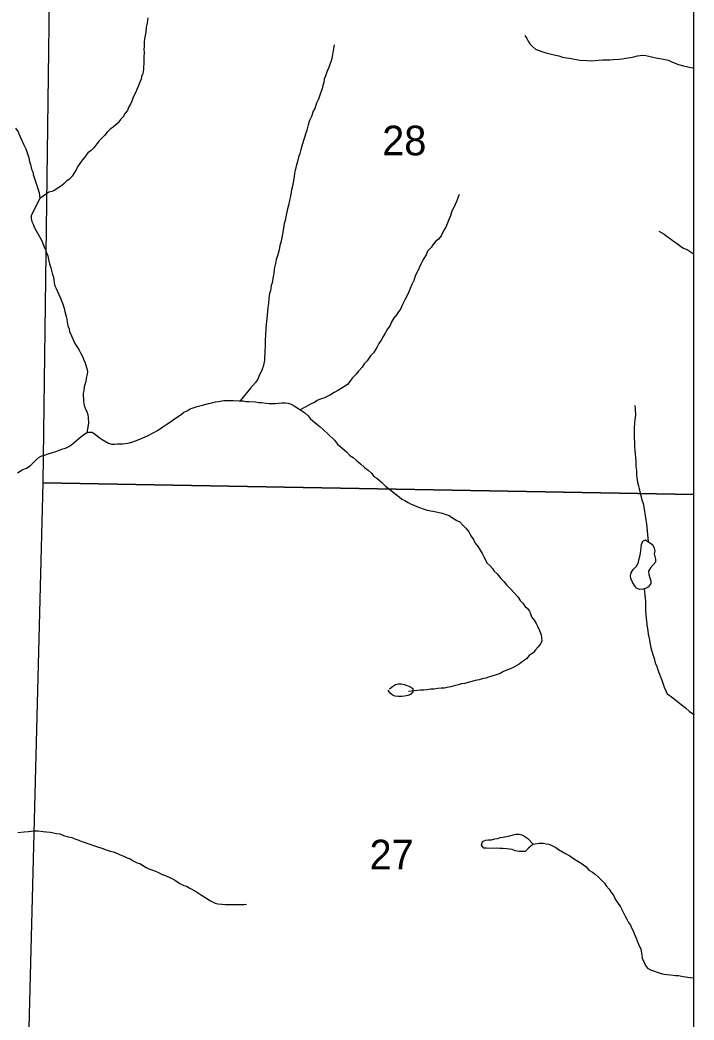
# Model space of a CAD drawing. Extents: x -10 to 158, y 8 to 33.
# Drawn here: x 30.449 to 31.4, y 15.63 to 17.041 of the extents above; entities that cross this region are included whole.
import ezdxf

# ---------------------------------------------------------------- set-up
doc = ezdxf.new("R2010")
doc.units = 0
for name, color, linetype in [('GM_X_Corporation', 7, 'Continuous'), ('GM_X_Minor_River', 7, 'Continuous'), ('GM_X_Section_Text', 7, 'Continuous')]:
    doc.layers.add(name, color=color, linetype=linetype)

msp = doc.modelspace()

# ---------------------------------------------------------------- linework, layer by layer
at = {"layer": 'GM_X_Corporation'}
for points in [[(29.6227, 14.1), (31.4, 14.1), (31.4, 20.9), (29.731, 20.9), (29.7244, 20.2649), (29.6982, 19.2496), (29.6981, 19.2461), (29.6974, 19.2018), (29.6957, 19.0991), (29.6992, 18.9556), (29.697, 18.9465), (29.6949, 18.8465), (29.6846, 18.5133), (29.6817, 18.3306), (29.6804, 18.2238), (29.6572, 17.4131), (29.6504, 16.6563), (29.6434, 16.3848), (29.6318, 15.4937)], [(31.4, 16.3712), (31.4, 17.3866), (30.4945, 17.3927), (30.4815, 16.3875)], [(31.4, 15.3662), (31.4, 16.3712), (30.4815, 16.3875), (30.4552, 15.381)]]:
    msp.add_lwpolyline(points, close=True, dxfattribs=at)
at = {"layer": 'GM_X_Minor_River'}
for points in [[(30.6294, 17.0437), (30.6284, 17.0361), (30.627, 17.0304), (30.6264, 17.0235), (30.6246, 17.014), (30.6243, 17.0095), (30.6244, 17.0034), (30.6238, 16.9992), (30.6242, 16.9954), (30.624, 16.9878), (30.6237, 16.9829), (30.6231, 16.9711), (30.6225, 16.9654), (30.6206, 16.9612), (30.62, 16.9574), (30.6181, 16.9532), (30.6156, 16.9467), (30.6138, 16.9429), (30.6123, 16.9391), (30.6101, 16.9349), (30.6083, 16.9303), (30.6069, 16.9261), (30.6051, 16.9219), (30.6021, 16.9173), (30.6007, 16.9131), (30.5973, 16.9092), (30.5944, 16.9043), (30.5907, 16.9004), (30.5874, 16.8958), (30.5806, 16.8896), (30.5765, 16.8865), (30.5721, 16.8826), (30.5684, 16.8776), (30.5606, 16.8703), (30.5576, 16.8661), (30.5532, 16.8603), (30.5494, 16.8568), (30.545, 16.8533), (30.5413, 16.8487), (30.5372, 16.8433), (30.5342, 16.8395), (30.5302, 16.8337), (30.5283, 16.8295), (30.525, 16.8242), (30.5225, 16.8203), (30.5187, 16.8161), (30.515, 16.8137), (30.5109, 16.8095), (30.5061, 16.8056), (30.5016, 16.8029), (30.4978, 16.8002), (30.4941, 16.7986), (30.4896, 16.7977), (30.4772, 16.7888), (30.4648, 16.7651), (30.4648, 16.7609), (30.4657, 16.7564), (30.4676, 16.7526), (30.4696, 16.7477), (30.477, 16.7342), (30.4798, 16.7293), (30.4837, 16.7195), (30.4857, 16.7158), (30.4865, 16.712), (30.4881, 16.7082), (30.4893, 16.7029), (30.4906, 16.6965), (30.4925, 16.6912)], [(31.1615, 17.019), (31.1642, 17.0145), (31.1662, 17.0108), (31.1685, 17.007), (31.172, 17.0033), (31.1762, 16.9996), (31.1838, 16.9967), (31.191, 16.9945), (31.1948, 16.9934), (31.2047, 16.9913), (31.2093, 16.9903), (31.2146, 16.9885), (31.2199, 16.9874), (31.2245, 16.9868), (31.229, 16.9861), (31.2336, 16.985), (31.2396, 16.984), (31.2495, 16.9834), (31.2552, 16.9831), (31.2654, 16.9841), (31.271, 16.9846), (31.2816, 16.9847), (31.2858, 16.9852), (31.2945, 16.9854), (31.2986, 16.9858), (31.3039, 16.987), (31.3103, 16.9879), (31.3149, 16.9888), (31.3201, 16.99), (31.3277, 16.9909), (31.3319, 16.9906), (31.3364, 16.9899), (31.3417, 16.9885), (31.3463, 16.9874), (31.352, 16.9864), (31.3569, 16.9857), (31.3634, 16.9839), (31.368, 16.9821), (31.3718, 16.9803), (31.3782, 16.9781), (31.3851, 16.976), (31.3896, 16.9749), (31.3934, 16.9742), (31.3984, 16.9732), (31.4, 16.9731)], [(30.8923, 17.0059), (30.8909, 16.9975), (30.8899, 16.9922), (30.8888, 16.9865), (30.8874, 16.9819), (30.8863, 16.9781), (30.8849, 16.9739), (30.8824, 16.9685), (30.8802, 16.962), (30.8784, 16.9571), (30.8777, 16.9525), (30.8763, 16.9483), (30.8752, 16.9438), (30.8731, 16.9376), (30.8716, 16.9331), (30.8702, 16.9289), (30.8672, 16.9235), (30.8651, 16.9159), (30.8625, 16.9121), (30.8604, 16.9048), (30.8575, 16.8991), (30.8557, 16.8926), (30.8539, 16.8854), (30.8489, 16.8709), (30.8467, 16.8629), (30.8453, 16.8579), (30.8439, 16.8526), (30.8421, 16.8472), (30.8407, 16.8411), (30.8389, 16.8346), (30.8371, 16.8286), (30.8364, 16.8244), (30.8358, 16.8194), (30.8344, 16.8114), (30.8333, 16.8065), (30.8323, 16.8012), (30.8306, 16.792), (30.8292, 16.7867), (30.8285, 16.781), (30.8267, 16.7745), (30.8246, 16.7654), (30.8232, 16.7578), (30.8218, 16.7536), (30.8204, 16.7437), (30.8191, 16.7361), (30.817, 16.7266), (30.8155, 16.7224), (30.8145, 16.7163), (30.8124, 16.7079), (30.8106, 16.7026), (30.8095, 16.6972), (30.8078, 16.6896), (30.8071, 16.6828), (30.8061, 16.679), (30.8047, 16.6698), (30.8036, 16.666), (30.8026, 16.6588), (30.8012, 16.655), (30.8002, 16.6482), (30.7995, 16.6409), (30.7989, 16.6352), (30.7979, 16.6242), (30.7969, 16.6155), (30.7966, 16.6109), (30.796, 16.6052), (30.7954, 16.5965), (30.7951, 16.5889), (30.7948, 16.584), (30.7949, 16.5791), (30.7946, 16.5753), (30.7943, 16.5707), (30.794, 16.565), (30.7938, 16.5601), (30.7931, 16.5563), (30.792, 16.5517), (30.7891, 16.5441), (30.7865, 16.5391), (30.7844, 16.5341), (30.7814, 16.5295), (30.7744, 16.5214), (30.7595, 16.5033)], [(30.4429, 16.8883), (30.4464, 16.8831), (30.448, 16.8793), (30.4496, 16.8748), (30.452, 16.8699), (30.4539, 16.8654), (30.4571, 16.859), (30.4595, 16.8518), (30.4615, 16.8465), (30.4627, 16.8409), (30.4639, 16.8367), (30.4655, 16.8303), (30.4671, 16.8265), (30.4675, 16.8228), (30.4715, 16.8115), (30.4727, 16.8073), (30.4747, 16.8016), (30.4759, 16.7971), (30.4768, 16.7933), (30.4772, 16.7888)], [(31.0689, 16.7947), (31.0664, 16.7886), (31.0649, 16.7848), (31.0624, 16.7795), (31.058, 16.7695), (31.0566, 16.7646), (31.0547, 16.7604), (31.0529, 16.7554), (31.0497, 16.7485), (31.0471, 16.7443), (31.0431, 16.7363), (31.0394, 16.7317), (31.0356, 16.7286), (31.0315, 16.7236), (31.029, 16.7197), (31.0241, 16.7147), (31.022, 16.7093), (31.019, 16.704), (31.0164, 16.7002), (31.0146, 16.6963), (31.0124, 16.691), (31.0095, 16.6849), (31.0073, 16.6806), (31.0048, 16.6734), (31.0019, 16.6677), (30.9997, 16.6619), (30.9975, 16.657), (30.9946, 16.6501), (30.992, 16.6459), (30.9887, 16.6394), (30.9858, 16.6329), (30.9833, 16.629), (30.9803, 16.6248), (30.9762, 16.6194), (30.9729, 16.6141), (30.9711, 16.6095), (30.9678, 16.6056), (30.9645, 16.5987), (30.9615, 16.5941), (30.9586, 16.5892), (30.9553, 16.5842), (30.9527, 16.5788), (30.9476, 16.5711), (30.9438, 16.5669), (30.9387, 16.56), (30.9346, 16.5554), (30.932, 16.5508), (30.9268, 16.5454), (30.9235, 16.5411), (30.9179, 16.5354), (30.9146, 16.5307), (30.9109, 16.5265), (30.906, 16.5234), (30.9023, 16.521), (30.8982, 16.5183), (30.8925, 16.5152), (30.8873, 16.5121), (30.8824, 16.5093), (30.8779, 16.5073), (30.8741, 16.5061), (30.8685, 16.5038), (30.8644, 16.501), (30.8606, 16.4998), (30.8445, 16.4909)], [(31.3502, 16.7429), (31.3578, 16.7385), (31.362, 16.7351), (31.3663, 16.7325), (31.3709, 16.7285), (31.3762, 16.7255), (31.3812, 16.7214), (31.3862, 16.7185), (31.3904, 16.7167), (31.3988, 16.7111), (31.4, 16.7103)], [(30.4925, 16.6912), (30.4934, 16.6871), (30.495, 16.6818), (30.4962, 16.678), (30.497, 16.6735), (30.4975, 16.6697), (30.4983, 16.6656), (30.4999, 16.6618), (30.5038, 16.6535), (30.5062, 16.6483), (30.5081, 16.6437), (30.5097, 16.64), (30.5109, 16.6354), (30.5125, 16.6294), (30.5142, 16.6226), (30.515, 16.6188), (30.5158, 16.6147), (30.5167, 16.609), (30.5183, 16.6049), (30.5191, 16.6011), (30.5215, 16.5951), (30.5234, 16.5909), (30.5266, 16.5845), (30.5301, 16.5785), (30.5324, 16.5748), (30.5344, 16.571), (30.5367, 16.5669), (30.5387, 16.5624), (30.5406, 16.5579), (30.5419, 16.5537), (30.5435, 16.5492), (30.5443, 16.545), (30.544, 16.5412), (30.5429, 16.5371), (30.5419, 16.5317), (30.5408, 16.5275), (30.5397, 16.523), (30.5391, 16.518), (30.5384, 16.5142), (30.5386, 16.5025), (30.5398, 16.4968), (30.541, 16.493), (30.5434, 16.4881), (30.5446, 16.484), (30.5454, 16.4795), (30.5456, 16.4719), (30.5432, 16.4581)], [(30.5557, 16.4558), (30.5607, 16.4517), (30.5649, 16.4487), (30.574, 16.4436), (30.5782, 16.4425), (30.5824, 16.4422), (30.5862, 16.4426), (30.5937, 16.4428), (30.5979, 16.4432), (30.6035, 16.4441), (30.6084, 16.4457), (30.616, 16.4485), (30.6223, 16.4512), (30.6291, 16.454), (30.6381, 16.4587), (30.643, 16.4615), (30.6493, 16.4658), (30.6561, 16.4704), (30.6613, 16.4739), (30.6669, 16.4778), (30.6763, 16.4841), (30.6804, 16.4872), (30.6849, 16.4895), (30.689, 16.4919), (30.695, 16.4942), (30.6988, 16.4954), (30.7029, 16.4963), (30.7067, 16.4971), (30.715, 16.4995), (30.7195, 16.5004), (30.7248, 16.502), (30.7285, 16.5024), (30.7365, 16.5037), (30.7402, 16.5041), (30.7455, 16.5039), (30.7497, 16.5039), (30.7584, 16.5033), (30.7637, 16.5034), (30.7675, 16.5027), (30.7717, 16.5024), (30.7811, 16.5018), (30.7861, 16.5012), (30.7899, 16.5009), (30.7959, 16.5002), (30.8005, 16.4995), (30.8092, 16.4997), (30.8186, 16.5006), (30.8232, 16.5007), (30.8273, 16.5), (30.8315, 16.4986), (30.8357, 16.4964), (30.8441, 16.4912), (30.8507, 16.4864), (30.8556, 16.4823), (30.8584, 16.4786), (30.8622, 16.4752), (30.868, 16.4704), (30.8726, 16.4667), (30.8768, 16.463), (30.8837, 16.4566), (30.893, 16.4477), (30.8968, 16.4425), (30.9033, 16.4373), (30.9103, 16.4309), (30.9145, 16.4261), (30.9191, 16.4235), (30.9233, 16.4198), (30.9295, 16.4146), (30.9352, 16.4094), (30.9402, 16.4057), (30.9456, 16.4009), (30.9483, 16.3967), (30.9525, 16.3942), (30.9591, 16.3886), (30.9648, 16.383), (30.9752, 16.3748), (30.9802, 16.3708), (30.984, 16.3682), (30.9879, 16.3648), (30.9921, 16.3626), (30.9966, 16.3601), (31.0008, 16.3575), (31.0047, 16.356), (31.0115, 16.3535), (31.0191, 16.3506), (31.0237, 16.3492), (31.0313, 16.3478), (31.0362, 16.3467), (31.0404, 16.3457), (31.045, 16.345), (31.0499, 16.3432), (31.0545, 16.3414), (31.0594, 16.3384), (31.0656, 16.3347), (31.0694, 16.3325), (31.074, 16.3281), (31.0779, 16.3236), (31.0821, 16.3184), (31.0852, 16.3131), (31.0887, 16.3079), (31.0911, 16.3026)], [(31.3166, 16.4969), (31.3171, 16.492), (31.3173, 16.4829), (31.3166, 16.4776), (31.3159, 16.4719), (31.3157, 16.4654), (31.3154, 16.4609), (31.3158, 16.4564), (31.3161, 16.4385), (31.3166, 16.4336), (31.3171, 16.4279), (31.3175, 16.4242), (31.318, 16.4173), (31.3181, 16.4109), (31.319, 16.4052), (31.3191, 16.3992), (31.3195, 16.395), (31.3204, 16.3886), (31.3216, 16.3833), (31.3225, 16.3795), (31.3237, 16.375), (31.3253, 16.3678), (31.3265, 16.3636), (31.3281, 16.3584), (31.3293, 16.3535), (31.3302, 16.3474), (31.3311, 16.3414), (31.3319, 16.3349), (31.3332, 16.3293), (31.3336, 16.3251), (31.3341, 16.3202), (31.3355, 16.3046)], [(30.4457, 16.4019), (30.4532, 16.4066), (30.4581, 16.4082), (30.4634, 16.4117), (30.4674, 16.4155), (30.4719, 16.4202), (30.476, 16.424), (30.4798, 16.4256), (30.4835, 16.4268), (30.4888, 16.4288), (30.4937, 16.43), (30.4997, 16.432), (30.5042, 16.4336), (30.5095, 16.4356), (30.5132, 16.4368), (30.5178, 16.4388), (30.5222, 16.4419), (30.5319, 16.4504), (30.5371, 16.4547), (30.542, 16.4578), (30.5462, 16.459), (30.5507, 16.4591), (30.5557, 16.4558)], [(31.0911, 16.3026), (31.0954, 16.2974), (31.0981, 16.2929), (31.1012, 16.288), (31.1028, 16.2842), (31.1055, 16.2801), (31.1079, 16.2748), (31.1121, 16.2711), (31.1156, 16.267), (31.1179, 16.2633), (31.1221, 16.2592), (31.1275, 16.2528), (31.1318, 16.2483), (31.1353, 16.2438), (31.1406, 16.2386), (31.1461, 16.2323), (31.1514, 16.2271), (31.1546, 16.2218), (31.1584, 16.2181), (31.1611, 16.2136), (31.165, 16.2106), (31.1677, 16.2065), (31.1693, 16.2027), (31.1709, 16.1986), (31.1743, 16.1941), (31.1774, 16.1892), (31.179, 16.1855), (31.1818, 16.1795), (31.1842, 16.1734), (31.185, 16.1697), (31.1854, 16.1647), (31.1832, 16.1605), (31.1803, 16.1563), (31.1762, 16.1521), (31.1729, 16.1478), (31.1676, 16.144), (31.1639, 16.1393), (31.1579, 16.1358), (31.1531, 16.1319), (31.146, 16.1276), (31.1411, 16.1253), (31.137, 16.1237), (31.1313, 16.1213), (31.1265, 16.1186), (31.1208, 16.1166), (31.1099, 16.1134), (31.1061, 16.1121), (31.1009, 16.1113), (31.0967, 16.1097), (31.0914, 16.1089), (31.0865, 16.1076), (31.0816, 16.106), (31.0768, 16.1048), (31.0718, 16.104), (31.0673, 16.1027), (31.0617, 16.1015), (31.0568, 16.0999), (31.0519, 16.0991), (31.0481, 16.0982), (31.0432, 16.0981), (31.0387, 16.0977), (31.0334, 16.0968), (31.0288, 16.0964), (31.0232, 16.0955), (31.0187, 16.0951), (31.0141, 16.095), (31.005, 16.0941), (30.9971, 16.0932)], [(31.3317, 16.3072), (31.342, 16.3002), (31.344, 16.2957), (31.3448, 16.2919), (31.3437, 16.2874), (31.3446, 16.2836), (31.3458, 16.2798), (31.3458, 16.276), (31.3384, 16.2676), (31.3358, 16.2633), (31.3363, 16.2584), (31.3375, 16.2539), (31.3391, 16.2494), (31.3392, 16.2456), (31.3358, 16.241), (31.3317, 16.2386), (31.328, 16.2378), (31.3234, 16.2373), (31.3189, 16.2391), (31.3161, 16.2429), (31.313, 16.2478), (31.311, 16.2527), (31.3102, 16.2564), (31.3113, 16.2606), (31.3142, 16.2656), (31.3187, 16.2702), (31.3216, 16.2752), (31.3223, 16.279), (31.3234, 16.2836), (31.3244, 16.2885), (31.3251, 16.2923), (31.3254, 16.2961), (31.3261, 16.3007), (31.3279, 16.3053), (31.3317, 16.3072)], [(31.3298, 16.2382), (31.3312, 16.225), (31.3316, 16.2212), (31.3314, 16.2147), (31.3315, 16.2068), (31.332, 16.2022), (31.3325, 16.1965), (31.3329, 16.1928), (31.3334, 16.1878), (31.335, 16.1788), (31.3355, 16.1742), (31.3367, 16.1682), (31.338, 16.1602), (31.3392, 16.155), (31.3405, 16.1501), (31.3425, 16.144), (31.3437, 16.1399), (31.3453, 16.1338), (31.3476, 16.1286), (31.3492, 16.124), (31.3512, 16.1176), (31.3528, 16.1139), (31.3548, 16.1094), (31.3564, 16.1037), (31.358, 16.0996), (31.3603, 16.0943), (31.3623, 16.0902), (31.3677, 16.0861), (31.373, 16.082), (31.3769, 16.079), (31.3819, 16.075), (31.388, 16.0705), (31.3938, 16.0649), (31.3987, 16.062), (31.4, 16.0604)], [(30.9706, 16.0969), (30.9747, 16.1003), (30.9788, 16.1031), (30.9825, 16.1043), (30.9867, 16.104), (30.9913, 16.1033), (30.9989, 16.1004), (31.0031, 16.0974), (31.0032, 16.0929), (30.9998, 16.089), (30.9961, 16.0875), (30.9916, 16.0866), (30.9878, 16.0862), (30.9832, 16.0861), (30.9783, 16.0868), (30.9745, 16.0882), (30.9707, 16.0912), (30.9687, 16.0953)], [(30.4462, 15.8946), (30.4549, 15.8955), (30.461, 15.896), (30.4647, 15.8961), (30.4693, 15.8966), (30.4749, 15.8967), (30.4818, 15.896)], [(30.4818, 15.896), (30.4863, 15.8953), (30.4916, 15.8947), (30.4962, 15.894), (30.5004, 15.8929), (30.5053, 15.8923), (30.5106, 15.8901), (30.5171, 15.8883), (30.5224, 15.8873), (30.5266, 15.8854), (30.5319, 15.8836), (30.5365, 15.8818), (30.5418, 15.8796), (30.5475, 15.8778), (30.5529, 15.876), (30.5571, 15.8746), (30.5643, 15.8724), (30.5708, 15.8699), (30.5765, 15.8681), (30.5803, 15.867), (30.5864, 15.8649), (30.5906, 15.8627), (30.5955, 15.8609), (30.6001, 15.8587), (30.6043, 15.8572), (30.6089, 15.8543), (30.6142, 15.8517), (30.618, 15.8506), (30.6218, 15.8481), (30.6272, 15.8451), (30.631, 15.8429), (30.6352, 15.8419), (30.6402, 15.8397), (30.6447, 15.8379), (30.6497, 15.8353), (30.6543, 15.8335), (30.6615, 15.8302), (30.6669, 15.8276), (30.6745, 15.8225), (30.6802, 15.8195), (30.684, 15.8185), (30.6886, 15.8159), (30.6966, 15.8115), (30.7039, 15.8071), (30.7127, 15.8011), (30.7177, 15.7978), (30.7246, 15.7949), (30.7284, 15.7938), (30.734, 15.7932), (30.739, 15.7929), (30.7428, 15.793), (30.7465, 15.7926), (30.7647, 15.793), (30.7685, 15.7934)], [(31.1732, 15.878), (31.1663, 15.8721), (31.1618, 15.8678), (31.1577, 15.8674), (31.1531, 15.8677), (31.1478, 15.8687), (31.1433, 15.8702), (31.1395, 15.8709), (31.1357, 15.8712), (31.1304, 15.8718), (31.1262, 15.8718), (31.1213, 15.8721), (31.1122, 15.8719), (31.1073, 15.8722), (31.1035, 15.8725), (31.1, 15.8766), (31.1018, 15.8816), (31.1056, 15.8835), (31.1101, 15.884), (31.1143, 15.8841), (31.1192, 15.8853), (31.1229, 15.8861), (31.1271, 15.8873), (31.1308, 15.8878), (31.1354, 15.8886), (31.1403, 15.8898), (31.1448, 15.891), (31.1486, 15.8919), (31.1531, 15.892), (31.1569, 15.8909), (31.1611, 15.8887), (31.1657, 15.8861), (31.1732, 15.878)], [(31.1732, 15.878), (31.1817, 15.8792), (31.187, 15.8793), (31.1912, 15.8786), (31.195, 15.8779), (31.2003, 15.8757), (31.2049, 15.8732), (31.2087, 15.8706), (31.2179, 15.8654), (31.2248, 15.8614), (31.2301, 15.8577), (31.2359, 15.854), (31.242, 15.8503), (31.2477, 15.8459), (31.2516, 15.8414), (31.2566, 15.8384), (31.2604, 15.8355), (31.2646, 15.8318), (31.2685, 15.828), (31.2735, 15.8228), (31.2762, 15.8191), (31.2804, 15.8146), (31.2828, 15.8108), (31.287, 15.8049), (31.289, 15.8003), (31.2921, 15.7958), (31.2964, 15.7895), (31.3027, 15.7763), (31.3054, 15.7722), (31.3074, 15.7673), (31.3105, 15.7636), (31.3117, 15.7598), (31.3144, 15.7557), (31.3164, 15.7497), (31.3183, 15.7455), (31.3196, 15.7414), (31.3219, 15.7369), (31.3251, 15.7297), (31.3263, 15.7218), (31.3268, 15.7172), (31.3295, 15.7108), (31.3315, 15.7067), (31.3346, 15.703), (31.3384, 15.7008), (31.3525, 15.6961), (31.3574, 15.6947), (31.3669, 15.6937), (31.3741, 15.6927), (31.3783, 15.6924), (31.3847, 15.6913), (31.3946, 15.6896), (31.3988, 15.6893), (31.4, 15.6893)]]:
    msp.add_lwpolyline(points, dxfattribs=at)

# ---------------------------------------------------------------- texts
at = {"layer": 'GM_X_Section_Text'}
for s, p in [('28', (30.9601, 16.8498)), ('27', (30.9422, 15.8423))]:
    msp.add_text(s, height=0.04186, rotation=0, dxfattribs=at).set_placement(p)

doc.saveas('drawing.dxf')
